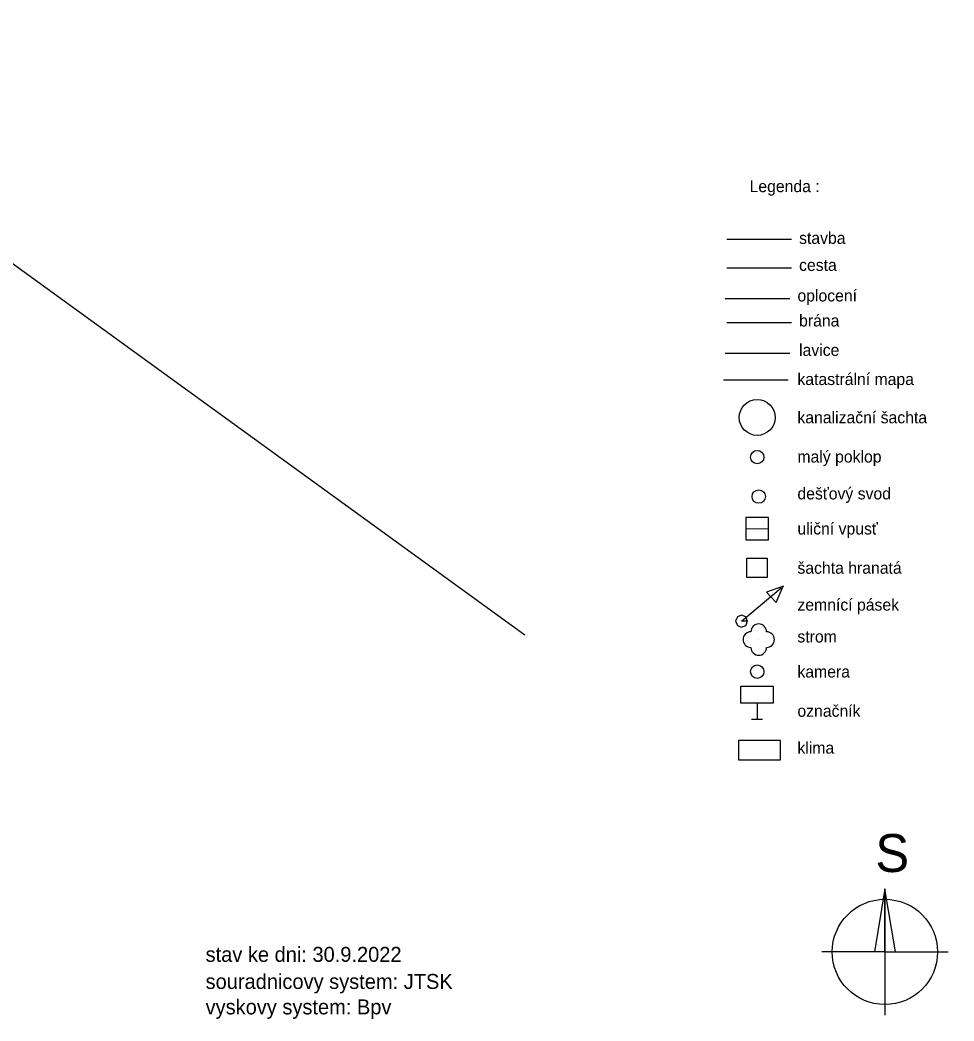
# Model space of a CAD drawing. Extents: x -805057 to -804930, y -994399 to -994240.
# Drawn here: x -804950.39 to -804929.56, y -994368.74 to -994346.41 of the extents above; entities that cross this region are included whole.
import ezdxf

# ---------------------------------------------------------------- set-up
doc = ezdxf.new("R2010")
doc.units = 0
doc.layers.add('Katastralni mapa', color=7, linetype='Continuous')
doc.layers.add('Legenda', color=7, linetype='Continuous')

# ---------------------------------------------------------------- blocks, each defined once
blk = doc.blocks.new('SEVER_1')
for p, q in [((6.27, 59.67), (-9.96, 1.05)), ((0, 0), (6.27, 59.67)), ((0, 0), (-59.67, 6.27)), ((0, 0), (-6.27, -59.67)), ((0, 0), (59.67, -6.27))]:
    blk.add_line(p, q)
blk.add_lwpolyline([(6.27, 59.67), (0, 0), (9.95, -1.05)], close=True)
blk.add_circle((0, 0), 50)

msp = doc.modelspace()

# ---------------------------------------------------------------- linework, layer by layer
at = {"layer": 'Katastralni mapa'}
msp.add_line((-804958.05, -994346.41), (-804939.13, -994360.125), dxfattribs=at)
at = {"layer": 'Legenda'}
for p, q in [((-804934.625, -994351.297), (-804933.185, -994351.297)), ((-804934.625, -994351.94), (-804933.185, -994351.94)), ((-804934.661, -994352.622), (-804933.221, -994352.622)), ((-804934.625, -994353.16), (-804933.185, -994353.16)), ((-804934.667, -994353.842), (-804933.221, -994353.842)), ((-804934.703, -994354.437), (-804933.258, -994354.437)), ((-804934.199, -994357.758), (-804933.699, -994357.757)), ((-804934.297, -994359.819), (-804933.413, -994359.078)), ((-804933.951, -994361.643), (-804933.951, -994362.01)), ((-804934.073, -994362.01), (-804933.828, -994362.01))]:
    msp.add_line(p, q, dxfattribs=at)
for points in [[(-804934.199, -994358.009), (-804933.698, -994358.008), (-804933.699, -994357.507), (-804934.2, -994357.508)], [(-804934.178, -994358.849), (-804934.18, -994358.418), (-804933.725, -994358.416), (-804933.724, -994358.848)], [(-804933.36, -994359.039), (-804933.741, -994359.175), (-804933.525, -994359.403), (-804933.372, -994359.04)], [(-804934.318, -994361.643), (-804933.583, -994361.643), (-804933.583, -994361.275), (-804934.318, -994361.275)], [(-804933.433, -994362.917), (-804933.433, -994362.485), (-804934.363, -994362.485), (-804934.363, -994362.917)]]:
    msp.add_lwpolyline(points, close=True, dxfattribs=at)
msp.add_lwpolyline([(-804934.163, -994359.819), (-804934.202, -994359.725), (-804934.297, -994359.686), (-804934.391, -994359.725), (-804934.43, -994359.819), (-804934.391, -994359.914), (-804934.297, -994359.953), (-804934.202, -994359.914), (-804934.163, -994359.819), (-804934.297, -994359.819)], dxfattribs=at)
for centre, radius in [((-804933.949, -994355.276), 0.4), ((-804933.949, -994356.161), 0.15), ((-804933.915, -994357.042), 0.15), ((-804933.915, -994360.232), 0.000175), ((-804933.949, -994360.948), 0.15)]:
    msp.add_circle(centre, radius, dxfattribs=at)
for centre, start, end in [((-804934.09, -994360.232), 90, 270), ((-804933.915, -994360.057), 0, 180), ((-804933.74, -994360.232), 270, 90), ((-804933.915, -994360.407), 180, 360)]:
    msp.add_arc(centre, 0.175, start, end, dxfattribs=at)

# ---------------------------------------------------------------- block references
at = {"layer": 'Legenda', "xscale": 0.02348648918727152, "yscale": 0.02348648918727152, "rotation": 5.999724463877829}
msp.add_blockref('SEVER_1', (-804931.101, -994367.2), dxfattribs=at)
msp.add_blockref('SEVER_1', (-804931.101, -994367.2), dxfattribs=at)
msp.add_blockref('SEVER_1', (-804931.101, -994367.2), dxfattribs=at)
msp.add_blockref('SEVER_1', (-804931.101, -994367.2), dxfattribs=at)
msp.add_blockref('SEVER_1', (-804931.101, -994367.2), dxfattribs=at)
msp.add_blockref('SEVER_1', (-804931.101, -994367.2), dxfattribs=at)
msp.add_blockref('SEVER_1', (-804931.101, -994367.2), dxfattribs=at)
msp.add_blockref('SEVER_1', (-804931.101, -994367.2), dxfattribs=at)

# ---------------------------------------------------------------- texts
at = {"layer": 'Legenda'}
for s, height, p in [('Legenda : ', 0.2629, (-804934.119, -994350.25)), ('stavba', 0.2629, (-804933.015, -994351.404)), ('cesta', 0.2629, (-804933.015, -994352.007)), ('oplocení', 0.2629, (-804933.052, -994352.689)), ('brána', 0.2629, (-804933.015, -994353.247)), ('lavice', 0.2629, (-804933.015, -994353.903)), ('katastrální mapa', 0.26289, (-804933.052, -994354.553)), ('kanalizační šachta', 0.26289, (-804933.052, -994355.407)), ('malý poklop', 0.26289, (-804933.052, -994356.282)), ('dešťový svod', 0.26289, (-804933.052, -994357.105)), ('uliční vpusť', 0.26289, (-804933.052, -994357.888)), ('šachta hranatá', 0.26289, (-804933.052, -994358.763)), ('zemnící pásek', 0.26289, (-804933.052, -994359.586)), ('strom', 0.2629, (-804933.052, -994360.296)), ('kamera', 0.2629, (-804933.052, -994361.078)), ('označník', 0.2629, (-804933.052, -994361.954)), ('klima', 0.2629, (-804933.052, -994362.777)), ('S', 0.846, (-804931.314, -994365.417)), ('S', 0.846, (-804931.314, -994365.417)), ('S', 0.846, (-804931.314, -994365.417)), ('S', 0.846, (-804931.314, -994365.417)), ('S', 0.846, (-804931.314, -994365.417)), ('S', 0.846, (-804931.314, -994365.417)), ('S', 0.846, (-804931.314, -994365.417)), ('S', 0.846, (-804931.314, -994365.417)), ('stav ke dni: 30.9.2022', 0.33403, (-804946.251, -994367.421)), ('souradnicovy system: JTSK', 0.33403, (-804946.251, -994368.026)), ('vyskovy system: Bpv', 0.33403, (-804946.251, -994368.593))]:
    msp.add_text(s, height=height, dxfattribs=at).set_placement(p)

doc.saveas('drawing.dxf')
